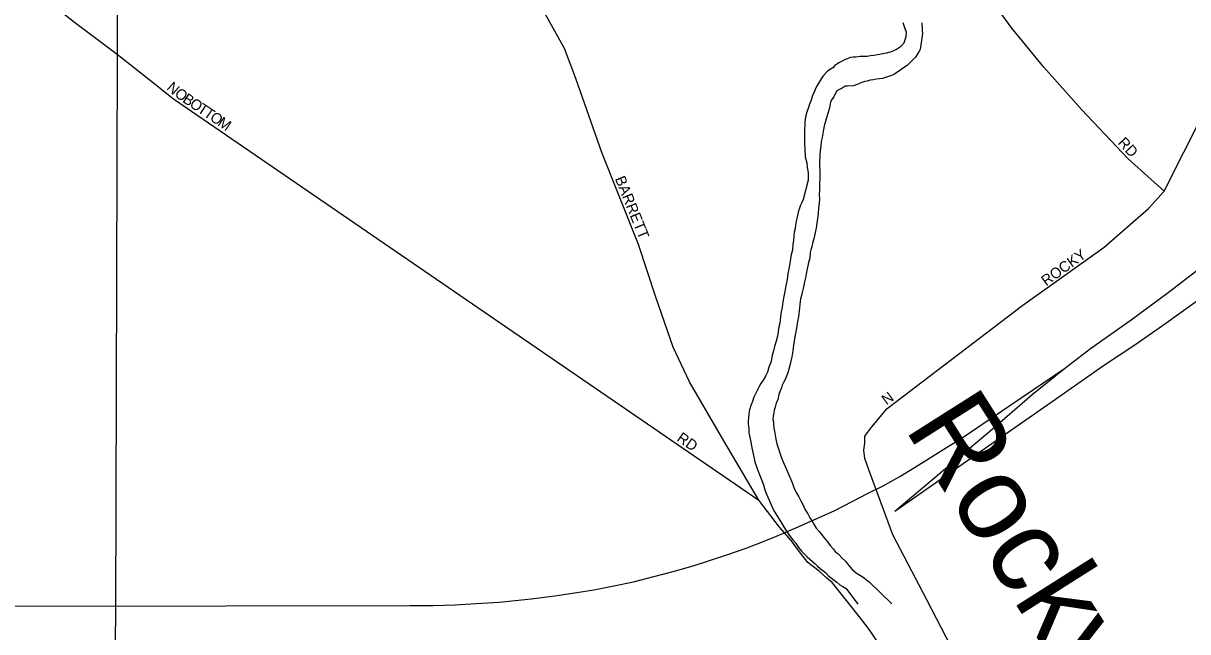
# Model space of a CAD drawing. Extents: x -561 to 1170, y 0 to 846.
# Drawn here: x 106.28 to 121.03, y 165.13 to 172.84 of the extents above; entities that cross this region are included whole.
import ezdxf

# ---------------------------------------------------------------- set-up
doc = ezdxf.new("R2010")
doc.units = 0
for name, color, linetype in [('GM_X_City_Street', 7, 'Continuous'), ('GM_X_City_Street_Text', 7, 'Continuous'), ('GM_X_County_Road', 7, 'Continuous'), ('GM_X_Major_River', 7, 'Continuous'), ('GM_X_Major_River_Text', 7, 'Continuous'), ('GM_X_Rail_Line', 7, 'Continuous'), ('GM_X_Township', 7, 'Continuous')]:
    doc.layers.add(name, color=color, linetype=linetype)

msp = doc.modelspace()

# ---------------------------------------------------------------- linework, layer by layer
at = {"layer": 'GM_X_City_Street'}
for points in [[(118.824, 163.409), (117.722, 165.539), (117.293, 166.361), (116.984, 167.199), (116.94, 167.331), (116.925, 167.434), (116.94, 167.522), (116.94, 167.61), (117.028, 167.728), (117.22, 167.963), (118.939, 169.271), (119.971, 170.008), (120.529, 170.494), (120.729, 170.714), (121.73, 172.702), (124.796, 179.218)], [(115.154, 167.554), (114.717, 168.301), (114.509, 168.74), (114.29, 169.374), (114.072, 170.04), (113.608, 171.206), (113.278, 172.143), (113.134, 172.522), (112.909, 172.923), (112.765, 173.211), (112.507, 173.493), (112.103, 173.765), (111.769, 173.956), (111.501, 174.228), (111.05, 174.738), (110.507, 175.324), (109.976, 175.943), (109.567, 176.372), (109.041, 176.921), (108.638, 177.257), (107.767, 177.87), (107.684, 177.919)], [(120.729, 170.714), (120.272, 171.124), (119.68, 171.749), (119.204, 172.288), (118.798, 172.779), (118.285, 173.492)], [(107.872, 172.133), (108.183, 171.884), (115.595, 166.799)], [(115.595, 166.799), (115.154, 167.554)], [(117.719, 163.269), (117.699, 163.67), (117.665, 163.875), (117.549, 164.193), (117.395, 164.463), (117.247, 164.754), (117.121, 164.975), (116.984, 165.174), (116.87, 165.324), (116.524, 165.759), (116.458, 165.814), (116.36, 165.902), (116.217, 166.011), (116.097, 166.165), (116.009, 166.285), (115.856, 166.46), (115.595, 166.799)]]:
    msp.add_lwpolyline(points, dxfattribs=at)
at = {"layer": 'GM_X_County_Road'}
msp.add_lwpolyline([(98.583, 175.707), (101.475, 174.965), (102.934, 174.66), (104.199, 174.4), (104.526, 174.323), (104.687, 174.276), (105.029, 174.127), (106.225, 173.358), (106.673, 173.059), (106.929, 172.856), (107.471, 172.453), (107.872, 172.133)], dxfattribs=at)
at = {"layer": 'GM_X_Major_River'}
for points in [[(117.42, 172.854), (117.449, 172.763), (117.46, 172.736), (117.456, 172.671), (117.446, 172.633), (117.431, 172.589), (117.388, 172.545), (117.34, 172.512), (117.302, 172.495), (117.265, 172.478), (117.238, 172.472), (117.211, 172.466), (117.162, 172.454), (117.13, 172.448), (117.097, 172.442), (117.054, 172.436), (117.011, 172.429), (116.968, 172.423), (116.924, 172.422), (116.876, 172.421), (116.827, 172.415), (116.789, 172.414), (116.757, 172.408), (116.714, 172.391), (116.681, 172.38), (116.649, 172.363), (116.617, 172.346), (116.585, 172.324), (116.558, 172.307), (116.532, 172.279), (116.499, 172.257), (116.467, 172.235), (116.42, 172.185), (116.398, 172.158), (116.335, 172.053), (116.314, 172.015), (116.299, 171.977), (116.283, 171.949), (116.273, 171.917), (116.257, 171.868), (116.237, 171.819), (116.221, 171.764), (116.201, 171.71), (116.186, 171.655), (116.176, 171.595), (116.177, 171.552), (116.172, 171.503), (116.173, 171.449), (116.174, 171.389), (116.175, 171.324), (116.177, 171.243), (116.184, 171.151), (116.202, 171.076), (116.208, 171.016), (116.214, 170.978), (116.22, 170.94), (116.221, 170.903), (116.222, 170.854), (116.156, 170.609), (116.141, 170.571), (116.125, 170.538), (116.109, 170.499), (116.099, 170.467), (116.089, 170.429)], [(117.659, 172.848), (117.666, 172.751), (117.667, 172.713), (117.638, 172.512), (117.622, 172.479), (117.58, 172.413), (117.527, 172.363), (117.474, 172.308), (117.415, 172.269), (117.378, 172.241), (117.345, 172.219), (117.313, 172.197), (117.276, 172.18), (117.238, 172.168), (117.2, 172.157), (117.163, 172.145), (117.125, 172.139), (117.087, 172.133), (117.049, 172.127), (117.006, 172.12), (116.968, 172.109), (116.936, 172.103), (116.898, 172.091), (116.86, 172.074), (116.828, 172.063), (116.79, 172.051), (116.72, 172.045), (116.688, 172.044), (116.65, 172.022), (116.607, 171.999), (116.58, 171.982), (116.544, 171.911), (116.517, 171.873), (116.502, 171.845), (116.487, 171.753), (116.467, 171.688), (116.451, 171.644), (116.441, 171.6), (116.426, 171.562), (116.416, 171.497), (116.406, 171.448), (116.396, 171.394), (116.386, 171.345), (116.382, 171.285)], [(116.382, 171.285), (116.372, 171.225), (116.368, 171.182), (116.368, 171.144), (116.364, 171.111), (116.364, 171.084), (116.365, 171.057), (116.365, 171.025), (116.366, 170.981), (116.367, 170.943), (116.367, 170.911), (116.368, 170.867), (116.364, 170.819), (116.364, 170.781), (116.365, 170.727), (116.361, 170.672), (116.362, 170.613), (116.358, 170.564), (116.353, 170.504), (116.349, 170.434), (116.339, 170.368), (116.33, 170.309), (116.32, 170.249), (116.31, 170.194), (116.3, 170.151), (116.29, 170.113), (116.275, 170.058), (116.265, 170.009), (116.255, 169.971), (116.244, 169.939), (116.24, 169.868), (116.225, 169.814), (116.195, 169.667), (116.185, 169.618), (116.175, 169.569), (116.165, 169.525), (116.155, 169.482), (116.145, 169.433), (116.135, 169.395), (116.125, 169.351), (116.116, 169.28), (116.111, 169.237), (116.106, 169.199), (116.102, 169.156), (116.092, 169.101), (116.082, 169.041), (116.073, 168.982), (116.058, 168.916), (116.048, 168.846), (116.033, 168.764), (116.024, 168.693), (116.014, 168.617), (115.999, 168.563), (115.989, 168.509), (115.974, 168.46), (115.964, 168.416), (115.948, 168.372), (115.928, 168.329), (115.907, 168.29), (115.891, 168.258), (115.881, 168.225), (115.865, 168.187), (115.85, 168.138), (115.835, 168.078), (115.814, 168.028), (115.804, 167.98), (115.788, 167.941), (115.784, 167.909), (115.779, 167.865), (115.774, 167.822), (115.78, 167.795), (115.781, 167.757), (115.787, 167.719), (115.793, 167.676), (115.806, 167.6), (115.817, 167.552), (115.824, 167.514), (115.835, 167.476), (115.847, 167.438), (115.864, 167.39), (115.881, 167.336), (115.904, 167.288), (115.977, 167.121), (115.994, 167.084), (116.022, 167.014), (116.045, 166.949), (116.073, 166.896), (116.101, 166.842), (116.129, 166.794), (116.152, 166.745), (116.18, 166.686), (116.214, 166.627), (116.242, 166.579), (116.27, 166.536), (116.292, 166.499), (116.32, 166.445), (116.359, 166.403), (116.392, 166.36), (116.425, 166.323), (116.464, 166.275), (116.498, 166.226)], [(116.089, 170.429), (116.079, 170.385), (116.069, 170.336), (116.059, 170.287), (116.055, 170.244), (116.045, 170.195), (116.04, 170.146), (116.036, 170.092), (116.026, 170.043), (116.022, 169.967), (116.007, 169.912), (115.997, 169.858), (115.987, 169.798), (115.977, 169.733), (115.962, 169.668), (115.953, 169.597), (115.938, 169.515), (115.923, 169.445), (115.914, 169.38), (115.898, 169.314), (115.889, 169.244), (115.874, 169.167), (115.87, 169.119), (115.865, 169.086), (115.86, 169.043), (115.85, 168.999), (115.84, 168.939), (115.831, 168.879), (115.816, 168.814), (115.795, 168.749), (115.78, 168.694), (115.765, 168.64), (115.75, 168.558), (115.724, 168.487), (115.704, 168.422), (115.678, 168.373), (115.651, 168.323), (115.62, 168.279), (115.599, 168.241), (115.578, 168.197), (115.552, 168.148), (115.531, 168.104), (115.516, 168.05), (115.495, 168.001), (115.474, 167.93), (115.46, 167.805), (115.461, 167.762), (115.468, 167.713), (115.469, 167.653), (115.481, 167.599), (115.493, 167.535), (115.505, 167.464), (115.522, 167.389), (115.546, 167.286), (115.58, 167.19), (115.609, 167.114), (115.632, 167.05), (115.654, 166.996), (115.672, 166.931), (115.694, 166.877), (115.711, 166.84), (115.728, 166.802), (115.751, 166.743), (115.785, 166.668), (115.83, 166.593), (115.886, 166.507), (115.93, 166.432), (115.98, 166.357), (116.025, 166.299), (116.064, 166.256), (116.097, 166.202), (116.136, 166.154), (116.174, 166.117), (116.208, 166.085), (116.241, 166.054), (116.274, 166.022), (116.307, 165.995), (116.34, 165.963), (116.373, 165.937), (116.406, 165.91), (116.439, 165.884), (116.472, 165.847), (116.516, 165.815), (116.549, 165.789), (116.582, 165.762), (116.621, 165.73), (116.659, 165.709), (116.703, 165.683), (116.849, 165.484)], [(116.498, 166.226), (116.536, 166.184), (116.564, 166.152), (116.603, 166.115), (116.652, 166.067), (116.691, 166.03), (116.73, 165.976), (116.779, 165.923), (116.829, 165.881), (116.862, 165.86), (116.906, 165.833), (116.933, 165.812), (116.961, 165.791), (116.994, 165.765), (117.278, 165.488)]]:
    msp.add_lwpolyline(points, dxfattribs=at)
at = {"layer": 'GM_X_Rail_Line'}
for points in [[(119.465, 168.471), (119.798, 168.723), (120.313, 169.085), (120.781, 169.434), (121.254, 169.796), (121.589, 170.045), (121.906, 170.324), (122.16, 170.576), (122.468, 170.918), (122.797, 171.292), (123.078, 171.651), (123.312, 171.971), (123.573, 172.36), (123.867, 172.821), (124.661, 174.108), (125.572, 175.579), (126.567, 177.187), (127.126, 178.108), (128.265, 179.939), (129.839, 182.493), (131.313, 184.879), (132.731, 187.186)], [(117.319, 166.663), (118.642, 167.585), (119.352, 168.081), (119.962, 168.509), (120.357, 168.771), (120.748, 169.044), (121.078, 169.279), (121.48, 169.558), (121.773, 169.782), (122.038, 169.992), (122.325, 170.231), (122.594, 170.455), (122.892, 170.71), (123.456, 171.19), (123.811, 171.505), (124.771, 172.395), (125.154, 172.751), (129.23, 176.633), (132.443, 179.671)], [(105.019, 165.459), (108.84, 165.464), (111.179, 165.466), (111.472, 165.468), (111.75, 165.476), (112.016, 165.49), (112.308, 165.51), (112.713, 165.551), (113.011, 165.589), (113.29, 165.631), (113.507, 165.665), (113.76, 165.716), (114.009, 165.768), (114.267, 165.834), (114.509, 165.898), (114.765, 165.971), (114.959, 166.032), (115.201, 166.113), (115.437, 166.195), (115.642, 166.273), (115.819, 166.345), (116.063, 166.45), (116.548, 166.667), (116.788, 166.789), (116.963, 166.88), (117.17, 166.984), (117.38, 167.102), (117.621, 167.248), (117.904, 167.424), (118.183, 167.601), (118.669, 167.93), (119.465, 168.471)], [(117.319, 166.663), (118.52, 167.676), (119.058, 168.139), (119.465, 168.471)]]:
    msp.add_lwpolyline(points, dxfattribs=at)
at = {"layer": 'GM_X_Township'}
msp.add_lwpolyline([(106.735, 180.917), (106.988, 179.888), (107.221, 179.671), (107.54, 179.692), (107.497, 179.671), (107.491, 178.031), (107.471, 172.453), (107.446, 165.386), (107.42, 162.758), (107.375, 158.106), (107.364, 154.516), (105.866, 154.485), (105.57, 154.137), (102.662, 151.915), (101.791, 151.915), (100.398, 152.372), (99.864, 151.952), (99.96, 147.535)], dxfattribs=at)

# ---------------------------------------------------------------- texts
at = {"layer": 'GM_X_City_Street_Text'}
for s, rotation, p in [('N', 318.5026, (108.087, 172.013)), ('O', 323.7988, (108.186, 171.926)), ('B', 326.2622, (108.287, 171.852)), ('O', 326.3031, (108.376, 171.793)), ('T', 326.3175, (108.475, 171.727)), ('T', 326.3071, (108.554, 171.674)), ('O', 326.3031, (108.633, 171.621)), ('M', 326.3099, (108.732, 171.555)), ('RD', 312.8801, (120.134, 171.323)), ('BARRETT', 292.1363, (113.77, 170.875)), ('ROCKY', 35.9422, (119.234, 169.508)), ('N', 36.8743, (117.214, 167.999)), ('RD', 325.4889, (114.547, 167.56))]:
    msp.add_text(s, height=0.135, rotation=rotation, dxfattribs=at).set_placement(p)
at = {"layer": 'GM_X_Major_River_Text'}
msp.add_text('Rocky', height=1.0806, rotation=302.3773, dxfattribs=at).set_placement((117.429, 167.718))

doc.saveas('drawing.dxf')
